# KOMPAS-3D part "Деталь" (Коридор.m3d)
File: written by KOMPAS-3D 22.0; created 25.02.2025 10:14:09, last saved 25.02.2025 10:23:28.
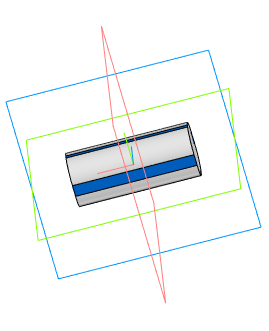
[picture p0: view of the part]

Document properties: Автор: Пользователь Windows; Полное имя файла: C:\Users\Student\Documents\Картошечка\База Сабнатика\Коридор\Коридор.m3d

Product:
- Part/product: Деталь
    Масса: 0.028645

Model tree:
1. Эскиз:1
2. Элемент выдавливания:1
     Расстояние 1 = 30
